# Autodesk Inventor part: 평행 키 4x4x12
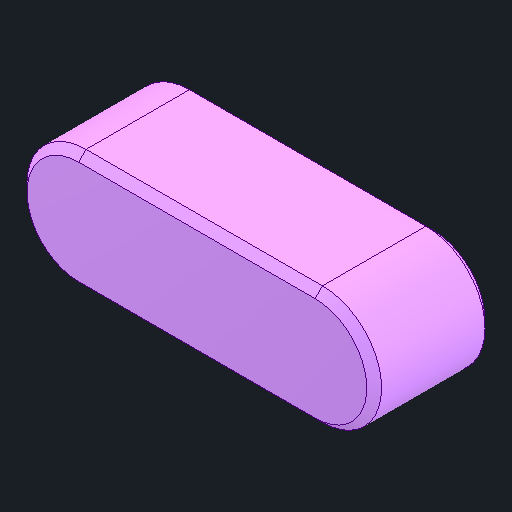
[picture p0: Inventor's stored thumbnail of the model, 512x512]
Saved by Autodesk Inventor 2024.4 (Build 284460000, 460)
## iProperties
Created: 2026-03
Part Number: 평행 키 4x4x12
Material: 강철, 연강
Description: 키 및 해당 키홈
Document SubType Name: Modeling
Designer: user
Density: 7.85 g/cm^3
Appearance: 기본값
Author: jhkim
Sending System: Autodesk Inventor 2026
Preprocessor: ST-DEVELOPER v20.1
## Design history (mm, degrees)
feature "Solid1"
node "솔리드1"
